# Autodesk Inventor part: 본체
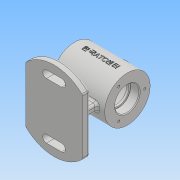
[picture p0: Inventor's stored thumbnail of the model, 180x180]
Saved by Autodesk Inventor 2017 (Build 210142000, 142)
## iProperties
Part Number: 본체
Material: 일반
Document SubType Name: Modeling
Designer: user
Density: 1 g/cm^3
Appearance: 기본값
Author: user
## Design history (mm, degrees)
sketch "스케치1"
  geometry: C1 r 30 at (0, 0); 1 further point
  constraints: 1 centre point, 1 coincident
  dimensions: "d0" = 60 diameter of C1
extrude "돌출1" new body sketch "스케치1" stored distance "d1" = 70; taper "d2" = 0 deg
sketch "스케치2"
  geometry: C1 r 30 at (0, 0) reference; C2 r 16 at (0, 0)
  constraints: 1 centre point, 1 coincident
  dimensions: "d3" = 32 diameter of C2
extrude "돌출2" cut sketch "스케치2" distance "d4" = 12; taper "d5" = 0 deg
sketch "스케치3"
  geometry: C1 r 16 at (0, 0) reference; C2 r 14 at (0, 0)
  constraints: 1 centre point, 1 coincident
  dimensions: "d6" = 28 diameter of C2
extrude "돌출3" cut sketch "스케치3" stored distance "d7" = 0; taper "d8" = 0 deg
sketch "스케치4"
  geometry: C1 r 25 at (0, 0); 1 further point
  constraints: 1 centre point, 1 coincident
  dimensions: "d9" = 50 diameter of C1
extrude "돌출4" cut sketch "스케치4" stored distance "d10" = 40; taper "d11" = 0 deg
fillet "모깎기1" dims "d12" = 3
chamfer "모따기1" distance "d13" = 1; stored, may be unused: second distance "d14" = 2, angle "d15" = 45 deg
node "작업 평면1"
sketch "스케치5"
  geometry: C1 r 10 at (0, 0); 1 further point
  constraints: 1 centre point, 1 coincident
  dimensions: "d17" = 20 diameter of C1
extrude "돌출5" join sketch "스케치5" stored distance "d18" = 40; taper "d19" = 0 deg
sketch "스케치6"
  geometry: C1 r 10 at (0, 0) reference; 1 further point
  constraints: 1 coincident
hole "구멍1" sketch "스케치6" at (0, 0) diameter "d20" = 10.106; stored, may be unused: countersink angle "d24" = 90 deg, drill point angle "d26" = 118 deg; dims "d21" = 24, "d22" = 4, "d23" = 2, "d25" = 32.3
node "작업 평면2"
sketch "스케치7"
  geometry: C1 r 52.5 at (0, 0); 1 further point
  constraints: 1 centre point, 1 coincident
  dimensions: "d28" = 105 diameter of C1
extrude "돌출6" join sketch "스케치7" distance "d29" = 10; taper "d30" = 0 deg
sketch "스케치8"
  geometry: L1 (37.5, -50)-(67.5, -50); L2 (67.5, -50)-(67.5, 50); L3 (67.5, 50)-(37.5, 50); L4 (37.5, 50)-(37.5, -50); L5 (37.5, -50)-(67.5, 50); L6 (67.5, -50)-(37.5, 50); L7 (-67.5, 50)-(-37.5, 50); L8 (-37.5, 50)-(-37.5, -50); L9 (-37.5, -50)-(-67.5, -50); L10 (-67.5, -50)-(-67.5, 50); L11 (-67.5, 50)-(-37.5, -50); L12 (-37.5, 50)-(-67.5, -50); C1 r 52.5 at (0, 0) reference; 4 further points
  constraints: 24 end point, 6 midpoint, 4 parallel, 2 horizontal, 2 horizontal alignment, 2 perpendicular
  dimensions: "d31" = 30 distance of L3.end L2.end; "d32" = 100 distance of L2.end L1.end; "d33" = 30 distance of L7.start L7.end; "d34" = 100 distance of L7.end L8.end; "d36" = 37.5 distance from line of C1.centre L4; "d37" = 37.5 distance from line of C1.centre L8
extrude "돌출7" cut sketch "스케치8" stored distance "d38" = 10; taper "d39" = 0 deg
sketch "스케치9"
  geometry: L1 (-25, -5)-(25, -5); L2 (25, -5)-(25, 5); L3 (25, 5)-(-25, 5); L4 (-25, 5)-(-25, -5); L5 (-25, -5)-(25, 5); L6 (25, -5)-(-25, 5); A1 r 52.5 centre (0, 0) between (37.5, 36.742) and (-37.5, 36.742) reference
  constraints: 12 end point, 2 midpoint, 2 parallel, 1 horizontal, 1 perpendicular
  dimensions: "d40" = 50 distance of L2.end L3.end; "d41" = 10 distance of L1.end L2.end
extrude "돌출8" join sketch "스케치9" stored distance "d42" = 10; taper "d43" = 0 deg
sketch "스케치10"
  geometry: L1 (-10, 37)-(10, 37); L2 (-10, 32)-(10, 32); L3 (10, 42)-(-10, 42); A1 r 52.5 centre (0, 0) between (-37.5, -36.742) and (37.5, -36.742) reference; A2 r 5 centre (-10, 37) between (-10, 42) and (-10, 32); A3 r 5 centre (10, 37) between (10, 32) and (10, 42); 1 further point
  constraints: 8 end point, 4 point on circle, 4 tangent, 2 centre point, 1 horizontal, 1 midpoint, 1 parallel, 1 vertical alignment
  dimensions: "d44" = 20 distance of L1.start L1.end; "d45" = 10 diameter of A3; "d46" = 37 distance of A1.centre point (0, 37)
extrude "돌출9" cut sketch "스케치10" stored distance "d47" = 10; taper "d48" = 0 deg
sketch "스케치11"
  geometry: C1 r 30 at (0, 0) reference; 1 further point
  constraints: 1 vertical alignment
  dimensions: "d49" = 23 distance of C1.centre point (0, 23)
hole "구멍2" sketch "스케치11" at (0, 23) diameter "d50" = 3.242; stored, may be unused: countersink angle "d54" = 90 deg, drill point angle "d56" = 118 deg; dims "d51" = 8, "d52" = 4, "d53" = 2, "d55" = 10
node "작업 평면3"
sketch "스케치12"
  geometry: L1 (-35, 30)-(-35, -30) reference; L2 (-35, 30)-(35, 30) reference; 2 further points
  constraints: 1 other
  dimensions: "d60" = 35 distance from line of L1 point (0, 0); "d61" = 30 distance from line of L2 point (0, 0)
feature "엠보싱1" sketch "스케치12" dims "d9" = 50, "d62" = 0.5, "d63" = 0
fillet "모깎기2" dims "d64" = 3
fillet "모깎기3" dims "d65" = 3
fillet "모깎기4" dims "d66" = 3
fillet "모깎기5" dims "d67" = 3
fillet "모깎기6" dims "d68" = 3
fillet "모깎기7" dims "d69" = 3
fillet "모깎기8" dims "d70" = 0.3
node "솔리드1"
mirror "미러1"
mirror "미러2"
pattern_circular "원형 패턴1" dims angle "d58" = 360 deg
mirror "미러3"
other parameters: "d16" = 33, "d27" = -62
